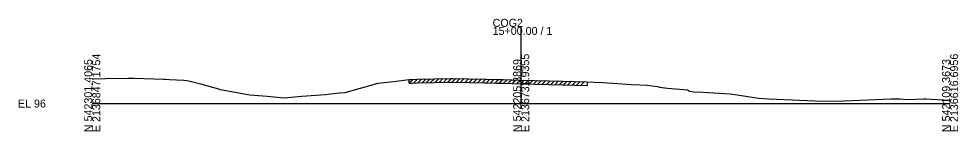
# Model space of a CAD drawing. Extents: x -13397 to 2303, y -10 to 39059.
# Drawn here: x -25.7 to 302.8, y 9990.3 to 10029.7 of the extents above; entities that cross this region are included whole.
import ezdxf

# ---------------------------------------------------------------- set-up
doc = ezdxf.new("R2010")
doc.units = 0
for name, color, linetype in [('RD_GPK_XS_Cell', 7, 'Continuous'), ('RD_XS_ExGround', 7, 'Continuous'), ('RD_XS_ExPaveRet', 7, 'Continuous'), ('RD_XS_TX_Elev_EX', 7, 'Continuous')]:
    doc.layers.add(name, color=color, linetype=linetype)

msp = doc.modelspace()

# ---------------------------------------------------------------- linework, layer by layer
at = {"layer": 'RD_GPK_XS_Cell'}
for p, q in [((150, 10000), (150, 10026.88)), ((0, 10000), (150, 10000)), ((150, 10000), (300, 10000))]:
    msp.add_line(p, q, dxfattribs=at)
at = {"layer": 'RD_XS_ExGround'}
for p, q in [((0, 10008.69), (0.51, 10008.71)), ((0.51, 10008.71), (4.6, 10008.79)), ((4.6, 10008.79), (12.59, 10008.96)), ((12.59, 10008.96), (14.6, 10008.89)), ((14.6, 10008.89), (24.86, 10008.53)), ((24.86, 10008.53), (25.56, 10008.5)), ((25.56, 10008.5), (27.04, 10008.43)), ((27.04, 10008.43), (32.03, 10008.17)), ((32.03, 10008.17), (33.03, 10008.05)), ((33.03, 10008.05), (34.24, 10007.82)), ((34.24, 10007.82), (37.85, 10006.95)), ((94.67, 10005.64), (99.98, 10007.12)), ((99.98, 10007.12), (105.31, 10007.77)), ((105.31, 10007.77), (110.83, 10008.41)), ((110.83, 10008.41), (111.87, 10008.45)), ((111.87, 10008.45), (113.85, 10008.53)), ((113.85, 10008.53), (125.29, 10008.8)), ((125.29, 10008.8), (126.22, 10008.82)), ((126.22, 10008.82), (137.31, 10008.6)), ((137.31, 10008.6), (137.71, 10008.59)), ((137.71, 10008.59), (141.38, 10008.48)), ((141.38, 10008.48), (143.73, 10008.41)), ((143.73, 10008.41), (146.87, 10008.31)), ((146.87, 10008.31), (150, 10008.23)), ((150, 10008.23), (164.44, 10007.9)), ((164.44, 10007.9), (173.11, 10007.65)), ((173.11, 10007.65), (175.47, 10007.56)), ((175.47, 10007.56), (178.42, 10007.4)), ((178.42, 10007.4), (183.76, 10007.01)), ((37.85, 10006.95), (44.17, 10005.11)), ((44.17, 10005.11), (44.58, 10004.99)), ((44.58, 10004.99), (45.49, 10004.84)), ((45.49, 10004.84), (55.09, 10003.03)), ((86.34, 10003.73), (88.4, 10003.94)), ((88.4, 10003.94), (94.67, 10005.64)), ((183.76, 10007.01), (188.43, 10006.65)), ((188.43, 10006.65), (191.51, 10006.54)), ((191.51, 10006.54), (194.08, 10006.51)), ((194.08, 10006.51), (197.65, 10005.98)), ((197.65, 10005.98), (198.43, 10005.75)), ((198.43, 10005.75), (201.23, 10005.46)), ((201.23, 10005.46), (208.17, 10004.79)), ((208.17, 10004.79), (208.85, 10004.35)), ((208.85, 10004.35), (210.35, 10004.1)), ((210.35, 10004.1), (213.7, 10004.01)), ((213.7, 10004.01), (223.04, 10003.42)), ((55.09, 10003.03), (61.2, 10002.63)), ((61.2, 10002.63), (67.12, 10002.07)), ((67.12, 10002.07), (73.29, 10002.57)), ((73.29, 10002.57), (81.58, 10003.2)), ((81.58, 10003.2), (86.34, 10003.73)), ((223.04, 10003.42), (225.57, 10003.03)), ((225.57, 10003.03), (233.04, 10001.91)), ((233.04, 10001.91), (236.77, 10001.63)), ((236.77, 10001.63), (255.38, 10000.9)), ((255.38, 10000.9), (263.05, 10001)), ((263.05, 10001), (279.24, 10001.7)), ((279.24, 10001.7), (282.53, 10001.71)), ((282.53, 10001.71), (284.99, 10001.47)), ((284.99, 10001.47), (290.74, 10001.61)), ((290.74, 10001.61), (291.59, 10001.69)), ((291.59, 10001.69), (293.53, 10001.58)), ((293.53, 10001.58), (300, 10001.14))]:
    msp.add_line(p, q, dxfattribs=at)
at = {"layer": 'RD_XS_ExPaveRet'}
for p, q in [((110.83, 10007.11), (112.18, 10008.46)), ((110.83, 10007.11), (110.83, 10008.41)), ((110.83, 10007.11), (111.87, 10007.15)), ((111.87, 10007.15), (113.85, 10007.23)), ((112.33, 10007.17), (113.69, 10008.53)), ((113.83, 10007.23), (115.16, 10008.56)), ((113.85, 10007.23), (125.29, 10007.5)), ((115.33, 10007.27), (116.66, 10008.6)), ((116.83, 10007.3), (118.16, 10008.63)), ((118.33, 10007.34), (119.66, 10008.67)), ((119.83, 10007.37), (121.16, 10008.7)), ((121.33, 10007.41), (122.66, 10008.74)), ((122.83, 10007.44), (124.16, 10008.77)), ((124.33, 10007.48), (125.66, 10008.81)), ((125.29, 10007.5), (126.22, 10007.52)), ((125.83, 10007.51), (127.12, 10008.81)), ((126.22, 10007.52), (137.31, 10007.3)), ((127.33, 10007.5), (128.6, 10008.78)), ((128.83, 10007.47), (130.1, 10008.75)), ((130.33, 10007.44), (131.6, 10008.72)), ((131.83, 10007.41), (133.1, 10008.69)), ((133.33, 10007.38), (134.6, 10008.66)), ((134.83, 10007.35), (136.1, 10008.63)), ((136.33, 10007.32), (137.6, 10008.6)), ((137.31, 10007.3), (137.71, 10007.29)), ((137.71, 10007.29), (141.38, 10007.18)), ((137.83, 10007.29), (139.09, 10008.55)), ((139.33, 10007.25), (140.59, 10008.51)), ((140.83, 10007.2), (142.09, 10008.46)), ((141.38, 10007.18), (143.73, 10007.11)), ((142.33, 10007.16), (143.59, 10008.42)), ((143.73, 10007.11), (146.87, 10007.01)), ((143.83, 10007.11), (145.09, 10008.37)), ((145.33, 10007.06), (146.59, 10008.32)), ((146.83, 10007.01), (148.1, 10008.28)), ((148.33, 10006.97), (149.6, 10008.24)), ((149.83, 10006.94), (151.1, 10008.21)), ((151.33, 10006.9), (152.6, 10008.17)), ((152.83, 10006.87), (154.1, 10008.14)), ((154.33, 10006.83), (155.6, 10008.1)), ((155.83, 10006.8), (157.1, 10008.07)), ((157.33, 10006.76), (158.6, 10008.03)), ((158.83, 10006.73), (160.1, 10008)), ((160.33, 10006.69), (161.6, 10007.96)), ((161.83, 10006.66), (163.1, 10007.93)), ((163.33, 10006.62), (164.6, 10007.89)), ((164.83, 10006.59), (166.1, 10007.85)), ((166.33, 10006.54), (167.6, 10007.81)), ((167.83, 10006.5), (169.1, 10007.77)), ((169.33, 10006.46), (170.6, 10007.72)), ((170.83, 10006.42), (172.1, 10007.68)), ((173.11, 10007.65), (173.11, 10006.35)), ((146.87, 10007.01), (150, 10006.93)), ((150, 10006.93), (164.44, 10006.6)), ((164.44, 10006.6), (173.11, 10006.35))]:
    msp.add_line(p, q, dxfattribs=at)

# ---------------------------------------------------------------- texts
at = {"layer": 'RD_GPK_XS_Cell'}
for s, p in [('COG2', (140, 10026.88)), ('15+00.00 / 1', (140, 10024.08)), ('EL 96', (-26, 9998.6))]:
    msp.add_text(s, height=2.8, dxfattribs=at).set_placement(p)
for s, p in [('E 2136847.1754', (2.8, 9990)), ('E 2136731.9355', (152.8, 9990)), ('E 2136616.6956', (302.8, 9990)), ('N 542301.4065', (0, 9990)), ('N 542205.3869', (150, 9990)), ('N 542109.3673', (300, 9990))]:
    msp.add_text(s, height=2.8, rotation=90, dxfattribs=at).set_placement(p)
at = {"layer": 'RD_XS_TX_Elev_EX'}
msp.add_text('104.23', height=1, rotation=90, dxfattribs=at).set_placement((150.75, 10009.23))

doc.saveas('drawing.dxf')
